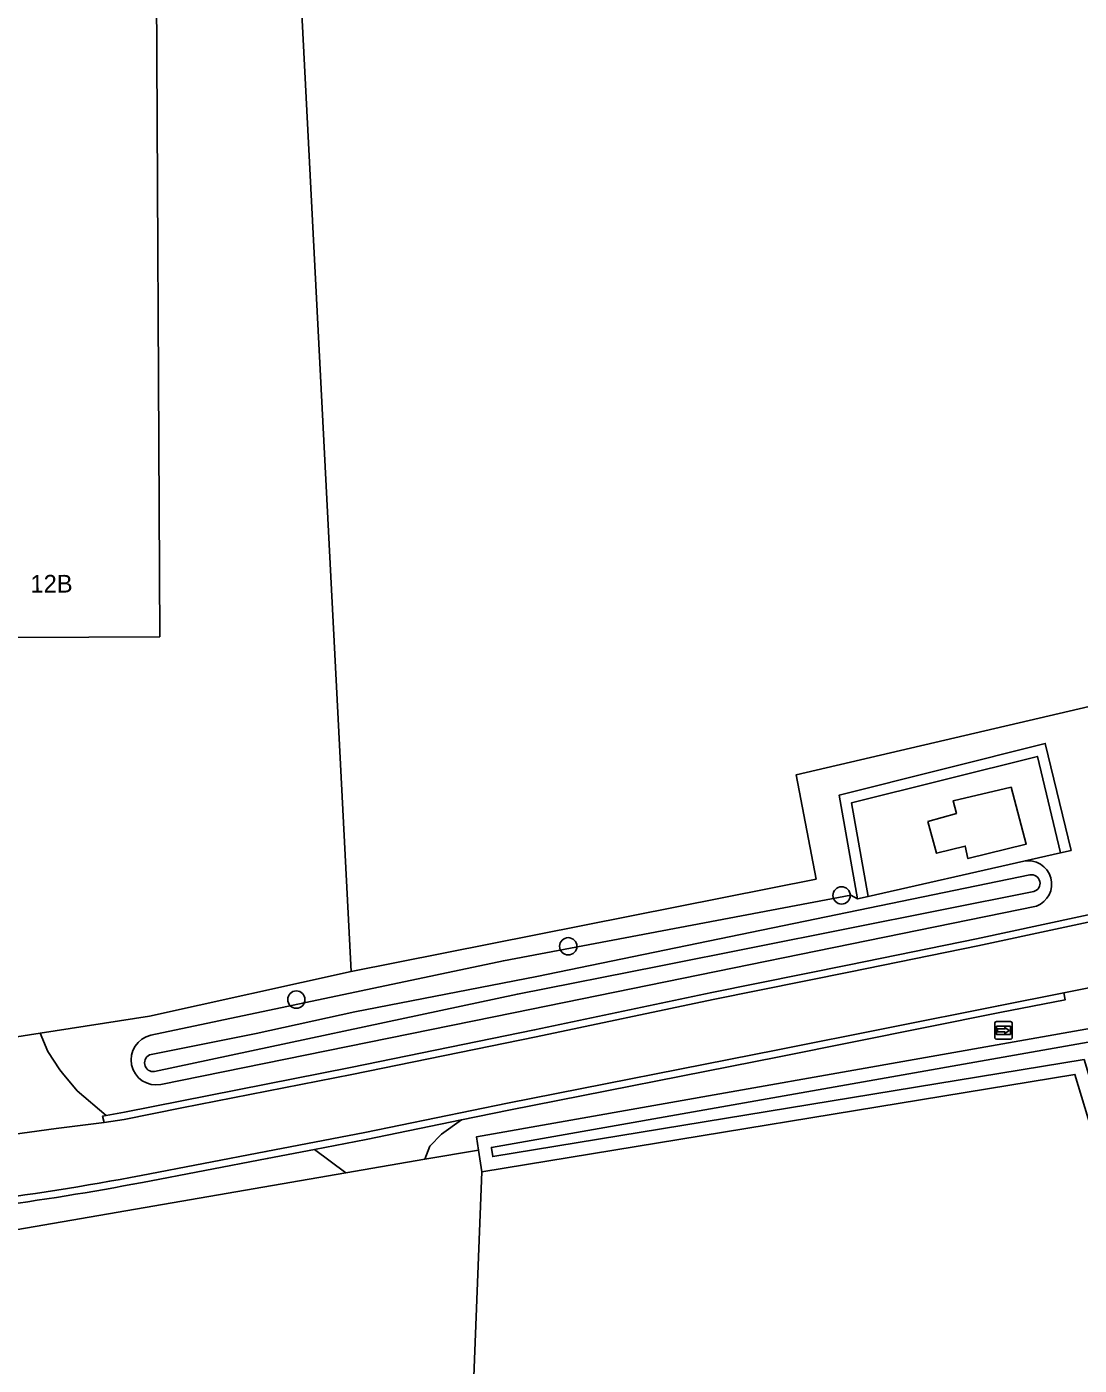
# Model space of a CAD drawing. Extents: x 162515 to 163909, y 388494 to 389773.
# Drawn here: x 163100.4 to 163159.8, y 388958.1 to 389033.6 of the extents above; entities that cross this region are included whole.
import ezdxf

# ---------------------------------------------------------------- set-up
doc = ezdxf.new("R2010")
doc.units = 0
for name, color, linetype in [('IMGEO_Berm_groen', 7, 'Continuous'), ('IMGEO_Boom', 7, 'Continuous'), ('IMGEO_Erf', 7, 'Continuous'), ('IMGEO_Grasland_agrarisch', 7, 'Continuous'), ('IMGEO_Grasland_overig', 7, 'Continuous'), ('IMGEO_Haag', 7, 'Continuous'), ('IMGEO_Loofbos', 7, 'Continuous'), ('IMGEO_Pand', 7, 'Continuous'), ('IMGEO_Pand_nummerreeks', 7, 'Continuous'), ('IMGEO_Rijbaan_lokaal_gesloten', 7, 'Continuous'), ('IMGEO_Rijbaan_lokaal_halfverhard', 7, 'Continuous'), ('IMGEO_Rijbaan_lokaal_open', 7, 'Continuous'), ('IMGEO_Voetpad_halfverhard', 7, 'Continuous'), ('IMGEO_Waterloop', 7, 'Continuous'), ('IMGEO_Wegwijzer', 7, 'Continuous')]:
    doc.layers.add(name, color=color, linetype=linetype)

msp = doc.modelspace()

# ---------------------------------------------------------------- linework, layer by layer
at = {"layer": 'IMGEO_Berm_groen'}
for points in [[(163125.918, 388970.212), (163125.807, 388970.958), (163161.159, 388977.199), (163161.379, 388976.501)], [(163122.893, 388969.691), (163125.918, 388970.212)]]:
    msp.add_lwpolyline(points, dxfattribs=at)
at = {"layer": 'IMGEO_Boom'}
for centre in [(163146.409, 388984.587), (163130.979, 388981.715), (163115.632, 388978.707)]:
    msp.add_circle(centre, 0.489, dxfattribs=at)
at = {"layer": 'IMGEO_Erf'}
msp.add_lwpolyline([(163126.1, 388968.984), (163125.918, 388970.212)], dxfattribs=at)
at = {"layer": 'IMGEO_Grasland_agrarisch'}
for points in [[(163118.731, 388980.29), (163115.27, 389047.574), (163113.418, 389081.706), (163113.14, 389101.685), (163111.562, 389101.645), (163110.682, 389093.418), (163109.205, 389090.774), (163109.47, 389081.706), (163110.799, 389062.102), (163104.432, 389063.174), (163104.431, 389067.813), (163104.401, 389071.251), (163104.273, 389079.255), (163104.148, 389082.618), (163099.917, 389084.74)], [(163180.426, 388914.304), (163177.974, 388921.494), (163176.525, 388925.031), (163166.878, 388950.374), (163159.581, 388974.479), (163126.1, 388968.984)], [(163130.113, 388950.183), (163126.78, 388949.576), (163125.622, 388956.459), (163126.1, 388968.984)]]:
    msp.add_lwpolyline(points, dxfattribs=at)
at = {"layer": 'IMGEO_Grasland_overig'}
for points in [[(163156.692, 388986.523), (163147.904, 388984.523)], [(163092.585, 388964.47), (163118.423, 388968.921)]]:
    msp.add_lwpolyline(points, dxfattribs=at)
at = {"layer": 'IMGEO_Haag'}
for points in [[(163147.318, 388984.39), (163146.281, 388990.258), (163157.912, 388993.169), (163159.363, 388987.131), (163158.778, 388986.998)], [(163158.778, 388986.998), (163157.47, 388992.44), (163146.969, 388989.812), (163147.904, 388984.523)], [(163147.904, 388984.523), (163147.318, 388984.39)]]:
    msp.add_lwpolyline(points, dxfattribs=at)
at = {"layer": 'IMGEO_Loofbos'}
for points in [[(163175.534, 389073.395), (163170.626, 389072.475), (163170.425, 389070.305), (163162.895, 388995.848), (163143.845, 388991.391), (163144.973, 388985.514), (163118.731, 388980.29)], [(163158.778, 388986.998), (163156.692, 388986.523)], [(163107.419, 388976.69), (163127.322, 388980.898), (163146.929, 388984.6), (163147.318, 388984.39)], [(163157.411, 388983.99), (163127.899, 388977.962), (163107.992, 388973.912)], [(163118.731, 388980.29), (163107.335, 388977.778), (163101.17, 388976.81)]]:
    msp.add_lwpolyline(points, dxfattribs=at)
for centre, radius, start, end in [((163156.947, 388985.227), 1.321, 290.54802, 101.1455), ((163107.724, 388975.305), 1.418, 102.41781, 280.89135)]:
    msp.add_arc(centre, radius, start, end, dxfattribs=at)
at = {"layer": 'IMGEO_Pand'}
for points in [[(163095.881, 388999.142), (163095.686, 389039.216), (163107.726, 389039.275), (163107.921, 388999.201), (163095.881, 388999.142)], [(163151.286, 388988.763), (163152.893, 388989.207), (163152.708, 388989.927), (163155.982, 388990.701), (163156.837, 388987.485), (163153.545, 388986.668), (163153.39, 388987.375), (163151.766, 388986.968), (163151.286, 388988.763)]]:
    msp.add_lwpolyline(points, dxfattribs=at)
at = {"layer": 'IMGEO_Rijbaan_lokaal_gesloten'}
for points in [[(163104.779, 388971.756), (163105.911, 388971.943), (163109.164, 388972.585), (163118.761, 388974.471), (163129.164, 388976.603), (163139.166, 388978.713), (163146.921, 388980.278), (163154.102, 388981.738), (163163.656, 388983.799), (163172.94, 388985.959)], [(163158.963, 388979.09), (163161.316, 388979.553)], [(163106.874, 388968.773), (163113.917, 388970.12), (163119.491, 388971.205), (163127.556, 388972.849), (163142.806, 388975.872), (163155.267, 388978.363), (163158.963, 388979.09)], [(163104.779, 388971.756), (163102.066, 388971.421), (163095.614, 388970.542)]]:
    msp.add_lwpolyline(points, dxfattribs=at)
msp.add_arc((163077.92, 389121.179), 155.132, 273.61082, 280.75683, dxfattribs=at)
at = {"layer": 'IMGEO_Rijbaan_lokaal_halfverhard'}
for points in [[(163172.849, 388986.349), (163163.572, 388984.19), (163154.022, 388982.13), (163146.842, 388980.67), (163139.083, 388979.104), (163129.084, 388976.995), (163118.681, 388974.863), (163105.937, 388972.354), (163104.899, 388972.165)], [(163124.953, 388971.91), (163127.634, 388972.457), (163142.884, 388975.48), (163155.345, 388977.971), (163159.04, 388978.698), (163158.963, 388979.09)], [(163116.66, 388970.246), (163119.571, 388970.813), (163124.953, 388971.91)], [(163106.949, 388968.38), (163113.993, 388969.727), (163116.66, 388970.246)]]:
    msp.add_lwpolyline(points, dxfattribs=at)
msp.add_arc((163077.903, 389121.3), 155.654, 274.30444, 280.7547, dxfattribs=at)
at = {"layer": 'IMGEO_Rijbaan_lokaal_open'}
for points in [[(163097.673, 388976.261), (163101.17, 388976.81)], [(163101.17, 388976.81), (163101.606, 388975.776), (163102.282, 388974.746), (163102.437, 388974.556), (163103.264, 388973.544), (163104.899, 388972.165)], [(163104.899, 388972.165), (163104.69, 388972.127), (163104.779, 388971.756)]]:
    msp.add_lwpolyline(points, dxfattribs=at)
at = {"layer": 'IMGEO_Voetpad_halfverhard'}
for points in [[(163122.893, 388969.691), (163123.16, 388970.437), (163123.835, 388971.112), (163124.953, 388971.91)], [(163116.66, 388970.246), (163118.423, 388968.921)], [(163118.423, 388968.921), (163122.893, 388969.691)]]:
    msp.add_lwpolyline(points, dxfattribs=at)
at = {"layer": 'IMGEO_Waterloop'}
for points in [[(163129.203, 388980.013), (163157.042, 388985.752)], [(163157.255, 388984.805), (163136.118, 388980.601), (163128.11, 388979.02), (163107.633, 388974.644)], [(163107.437, 388975.611), (163113.361, 388976.795), (163118.936, 388978.006), (163129.203, 388980.013)], [(163181.149, 388914.477), (163181.106, 388914.605), (163180.866, 388915.308), (163178.668, 388921.754), (163177.214, 388925.303), (163167.579, 388950.613), (163160.102, 388975.315), (163126.722, 388969.836), (163126.65, 388970.321), (163126.645, 388970.354), (163160.648, 388976.357), (163160.673, 388976.278), (163168.917, 388950.138), (163176.605, 388927.294), (163178.95, 388921.57), (163180.417, 388917.433), (163180.49, 388917.18)]]:
    msp.add_lwpolyline(points, dxfattribs=at)
for centre, radius, start, end in [((163157.127, 388985.274), 0.486, 285.23068, 100.12145), ((163107.557, 388975.132), 0.494, 104.05169, 278.86427)]:
    msp.add_arc(centre, radius, start, end, dxfattribs=at)
at = {"layer": 'IMGEO_Wegwijzer'}
for p, q in [((163155.053, 388976.567), (163155.053, 388977.367)), ((163155.053, 388977.367), (163155.053, 388976.567)), ((163155.153, 388977.467), (163155.943, 388977.467)), ((163155.943, 388977.467), (163155.153, 388977.467)), ((163156.043, 388977.367), (163156.043, 388976.567)), ((163156.043, 388976.567), (163156.043, 388977.367)), ((163155.943, 388976.467), (163155.153, 388976.467)), ((163155.153, 388976.467), (163155.943, 388976.467))]:
    msp.add_line(p, q, dxfattribs=at)
for points in [[(163155.154, 388977.199), (163155.942, 388977.199), (163155.942, 388976.735), (163155.154, 388976.735), (163155.154, 388977.199)], [(163155.219, 388977.051), (163155.219, 388976.967), (163155.219, 388976.883), (163155.63, 388976.883), (163155.63, 388976.8), (163155.877, 388976.967), (163155.63, 388977.134), (163155.63, 388977.051), (163155.219, 388977.051)]]:
    msp.add_lwpolyline(points, dxfattribs=at)
for centre, start, end in [((163155.153, 388977.367), 90, 180), ((163155.153, 388977.367), 90, 180), ((163155.943, 388977.367), 0, 90), ((163155.943, 388977.367), 360, 90), ((163155.153, 388976.567), 180, 270), ((163155.153, 388976.567), 180, 270), ((163155.943, 388976.567), 270, 0), ((163155.943, 388976.567), 270, 0)]:
    msp.add_arc(centre, 0.1, start, end, dxfattribs=at)

# ---------------------------------------------------------------- texts
at = {"layer": 'IMGEO_Pand_nummerreeks'}
msp.add_text('12B', height=1, rotation=0.28077, dxfattribs=at).set_placement((163100.624, 389001.685))

doc.saveas('drawing.dxf')
